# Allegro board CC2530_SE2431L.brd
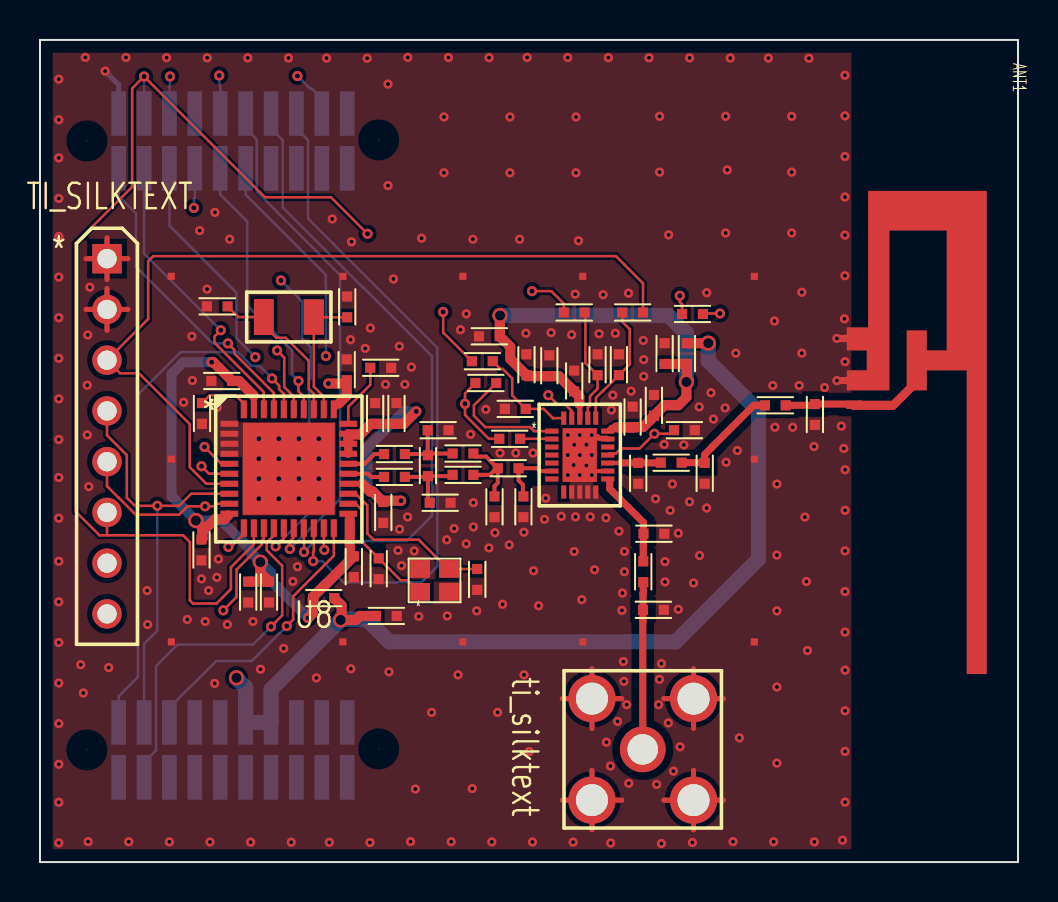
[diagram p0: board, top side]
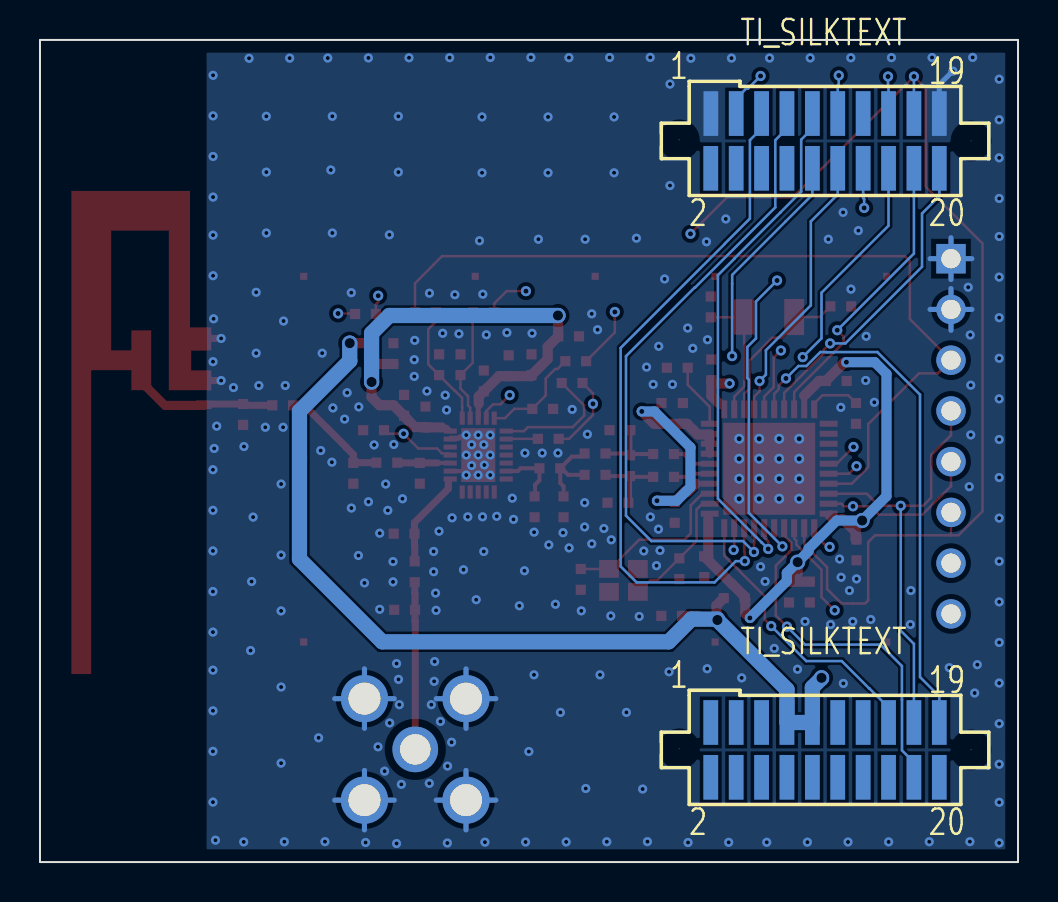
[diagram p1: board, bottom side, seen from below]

Outline 48.92 x 41.15 mm; copper layers: TOP, GND, SIGNAL_A, BOTTOM. Coordinates in mm from the lower left corner of the outline.
Outline path: rectangle 0,0 48.92,41.15

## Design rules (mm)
nets with their own width: min track width 0.356; nets N15960596 N15960606 N15982649 N15984570 VCC_SL2341 VDDRF
nets with their own width: min track width 0.508; nets VDD_CC253X

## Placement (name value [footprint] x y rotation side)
ANT1  N/A  [ANT_IIFA_CC2420_62MIL]  41.05 26.26 270 top
C1  1.0uF  [0402]  17.32 12.32 0 top
C2  1.0uF  [0402]  11.46 13.51 270 top
C3  1.0uF  [0402]  10.41 13.51 270 top
C4  1.0uF  [0402]  24.33 24.89 90 top
C5  1.0uF  [0402]  22.48 26.31 180 top
C6  12pF  [0402]  15.37 27.79 90 top
C7  12pF  [0402]  8.86 27.81 180 top
C47  1.0pF  [0402]  19.91 21.62 180 top
C48  1.0pF  [0402]  21.16 19.38 180 top
C52  2.2pF  [0402]  23.42 19.71 180 top
C62  2.2uF  [0402]  30.71 22.86 90 top
C63  100nF  [0402]  31.24 25.45 90 top
C64  10pF  [0402]  29.64 22.28 90 top
C65  10pF  [0402]  26.72 24.08 90 top
C66  2.2uF  [0402]  25.48 24.84 90 top
C71  1.8pF  [0402]  29.92 19.46 90 top
C72  1.8pF  [0402]  33.25 19.46 90 top
C76  DNI  [0402]  28.96 24.89 90 top
C77  DNI  [0402]  27.89 24.89 90 top
C79  DNI  [0402]  23.77 22.68 180 top
C83  1.8pF  [0402]  30.71 16.43 180 top
C84  1.8pF  [0402]  30.68 12.62 180 top
C85  DNI  [0402]  32.23 21.62 0 top
C101  0.1uF  [0402]  8.08 15.62 270 top
C211  0.1uF  [0402]  15.7 14.78 270 top
C221  15pF  [0402]  16.94 14.68 270 top
C231  15pF  [0402]  21.87 14.15 270 top
C241  0.1uF  [0402]  17.17 17.5 270 top
C251  18pF  [0402]  17.73 19.28 0 top
C261  18pF  [0402]  17.73 20.42 0 top
C281  0.1uF  [0402]  16.76 22.45 90 top
C282  220pF  [0402]  17.83 22.45 90 top
C311  0.1uF  [0402]  15.34 24.64 90 top
C391  1.0uF  [0402]  9.09 24.08 180 top
C401  1.0uF  [0402]  8.1 22.45 90 top
C402  TBD  [0402]  19.41 19.84 90 top
C403  TBD  [0402]  22.73 17.78 270 top
C404  TBD  [0402]  24.18 17.78 270 top
C405  TBD  [0402]  38.76 22.4 270 top
FB1  1K ohm @ 100MHz  [FB_0402]  14.2 13.21 180 top
FB2  1K ohm @ 100MHz  [FB_0402]  32.36 25.45 270 top
J5  3 GHz  [SMA_THVT_5-1814832-1]  30.15 5.64 270 top
L3  2.0nH  [0402]  20.02 17.98 0 top
L4  2.0nH  [0402]  21.16 20.45 180 top
L8  1.2nH  [0402]  31.57 19.99 180 top
L10  1.2nH  [0402]  30.18 14.53 90 top
P1  SFM-110-02-L-D-A  [CON_SMVT_2X10_50_F_SFM_FLIP_CC]  9.65 36.09 180 bottom
P2  SFM-110-02-L-D-A  [CON_SMVT_2X10_50_F_SFM_FLIP_CC]  9.65 5.61 180 bottom
P3  1x8 THVT  [HDR_THVT_1X8_100_M]  3.35 30.2 0 top
R28  2.2k  [0402]  22.3 23.98 0 top
R29  1.2k  [0402]  23.49 21.18 0 top
R32  0  [0402]  29.64 27.51 180 top
R43  0  [0402]  26.72 27.51 0 top
R45  0  [0402]  22.12 25.07 0 top
R48  0  [0402]  32.64 27.43 0 top
R301  56.2K  [0402]  17.04 24.74 0 top
R302  0  [0402]  36.78 22.86 0 top
U5  SE2431L-R  [QFN_24_EP1P70X2P70]  27 20.37 0 top
U7  CC2530F256RHA  [PVQFN_RHA40_EP4P50SQ]  12.45 19.68 270 top
U8  RF SHIELD  [SH_BMI-S-209_1P156X728]  6.07 10.52 0 top
Y5  32.768kHz  [XTAL_130X63X36]  12.45 27.28 180 top
Y6  32MHz 12pF  [XTAL_4_SM_83X67X20]  19.74 14.1 0 top

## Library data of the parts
ANT1 = ANT_IIFA_CC2420_62mil
C1-C5 = CAP_NP: alternate symbols: (0402_SMALL)
C6 C7 = CAP_NP: tolerance: 5%
C47 C48 C52 C71 C72 C83 C84 = CAP_NP: tolerance: NPO +/-0.25pF
C62-C66 C76 C77 C79 C85 C101 C211 C241 C281 C282 C311 C391 C401 = CAP0402
C221 C231 C251 C261 = CAP_NP: tolerance: +/-5%
C402-C405 = CAP_NP
FB1 FB2 = FERRITE_BEAD
J5 = SMA_5P
L3 L4 L8 L10 = IND0402
P1 P2 = CON_SMVT_2x10_50_F_SFM_FLIP_CC
P3 = HEADER_1x8
R28 R29 R32 R43 R45 R48 R302 = RES0402: tolerance: 5%
R301 = RES0402: tolerance: 1%
U5 = SE2431L_QFN24
U7 = CC2530Fxx_RHA40
U8 = RF_SHIELD_12P
Y5 = XTAL_32p768kHz_CC7V_T1A
Y6 = XTAL_4_FA-128_32MHz_10ppm_12pF

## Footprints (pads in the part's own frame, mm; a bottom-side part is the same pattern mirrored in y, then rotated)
0402
  rect 0.508x0.508 smd: 1(-0.521,0) 2(0.521,0)
ANT_IIFA_CC2420_62MIL
  rect 0.33x1.397 smd: 1(3.404,0) 2(2.108,0) 3(0,0)
CON_SMVT_2X10_50_F_SFM_FLIP_CC
  round 0.025 hole 1.346 unplated: (-7.303,0.051) (7.303,0)
  rect 0.737x2.235 smd: 1(-5.715,1.372) 2(-5.715,-1.372) 3(-4.445,1.372) 4(-4.445,-1.372) 5(-3.175,1.372) 6(-3.175,-1.372) 7(-1.905,1.372) 8(-1.905,-1.372) 9(-0.635,1.372) 10(-0.635,-1.372) 11(0.635,1.372) 12(0.635,-1.372) 13(1.905,1.372) 14(1.905,-1.372) 15(3.175,1.372) 16(3.175,-1.372) 17(4.445,1.372) 18(4.445,-1.372) 19(5.715,1.372) 20(5.715,-1.372)
FB_0402
  rect 0.508x0.508 smd: 1(-0.521,0) 2(0.521,0)
HDR_THVT_1X8_100_M
  rect 1.473x1.473 hole 0.965: 1(0,0)
  round 1.473 hole 0.965: 2(0,-2.54) 3(0,-5.08) 4(0,-7.62) 5(0,-10.16) 6(0,-12.7) 7(0,-15.24) 8(0,-17.78)
PVQFN_RHA40_EP4P50SQ
  rect 0.305x0.889 smd: 1(-2.25,-2.974) 2(-1.75,-2.974) 3(-1.25,-2.974) 4(-0.749,-2.974) 5(-0.249,-2.974) 6(0.249,-2.974) 7(0.749,-2.974) 8(1.25,-2.974) 9(1.75,-2.974) 10(2.25,-2.974) 21(2.25,2.974) 22(1.75,2.974) 23(1.25,2.974) 24(0.749,2.974) 25(0.249,2.974) 26(-0.249,2.974) 27(-0.749,2.974) 28(-1.25,2.974) 29(-1.75,2.974) 30(-2.25,2.974)
  rect 0.889x0.305 smd: 11(2.974,-2.25) 12(2.974,-1.75) 13(2.974,-1.25) 14(2.974,-0.749) 15(2.974,-0.249) 16(2.974,0.249) 17(2.974,0.749) 18(2.974,1.25) 19(2.974,1.75) 20(2.974,2.25) 31(-2.974,2.25) 32(-2.974,1.75) 33(-2.974,1.25) 34(-2.974,0.749) 35(-2.974,0.249) 36(-2.974,-0.249) 37(-2.974,-0.749) 38(-2.974,-1.25) 39(-2.974,-1.75) 40(-2.974,-2.25)
  rect 4.597x4.597 smd: 41(0,0)
QFN_24_EP1P70X2P70
  rect 0.66x0.254 smd: 1(-1.4,1.199) 2(-1.4,0.8) 3(-1.4,0.401) 4(-1.4,0) 5(-1.4,-0.401) 6(-1.4,-0.8) 7(-1.4,-1.199) 13(1.4,-1.199) 14(1.4,-0.8) 15(1.4,-0.401) 16(1.4,0) 17(1.4,0.401) 18(1.4,0.8) 19(1.4,1.199)
  rect 0.254x0.66 smd: 8(-0.8,-1.849) 9(-0.401,-1.849) 10(0,-1.849) 11(0.401,-1.849) 12(0.8,-1.849) 20(0.8,1.849) 21(0.401,1.849) 22(0,1.849) 23(-0.401,1.849) 24(-0.8,1.849)
  rect 1.702x2.692 smd: EPAD(0,0)
SH_BMI-S-209_1P156X728
  rect 0.356x0.356 smd: 1(0.5,0.5) 2(9.081,0.5) 3(15.08,0.5) 4(21.079,0.5) 5(29.66,0.5) 6(29.66,9.649) 7(29.66,18.801) 8(21.079,18.801) 9(15.08,18.801) 10(9.081,18.801) 11(0.5,18.801) 12(0.5,9.649)
SMA_THVT_5-1814832-1
  round 2.286 hole 1.524: 1(0,0)
  round 2.362 hole 1.6: 2(-2.54,2.54) 3(2.54,2.54) 4(2.54,-2.54) 5(-2.54,-2.54)
XTAL_4_SM_83X67X20
  rect 0.991x0.889 smd: 1(-0.724,-0.574) 2(0.724,-0.574) 3(0.724,0.574) 4(-0.724,0.574)
XTAL_130X63X36
  rect 0.991x1.803 smd: 1(1.25,0)
  rect 1.016x1.778 smd: 2(-1.25,0)

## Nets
GND: ANT1.2(G2) ANT1.3(G1) C1.2 C2.2 C3.2 C4.2 C5.2 C6.2 C7.2 C47.1 C62.2 C63.2 C64.2 C65.2 C66.2 C71.1 C72.1 C76.2 C77.2 C79.2 C83.1 C84.1 C85.2 C101.2 C211.2 C221.2 C231.2 C241.2 C281.2 C282.2 C311.2 C391.2 C401.1 C403.2 C404.2 C405.2 J5.2(SHIELD1) J5.3(SHIELD2) J5.4(SHIELD3) J5.5(SHIELD4) L3.2 P1.1 P1.19 P3.1 P3.2 R301.2 U5.9(GND#9) U5.10(GND#10) U5.11(GND#11) U5.12(GND#12) U5.14(GND#14) U5.18(GND#18) U5.EPAD U7.1(GND#1) U7.2(GND#2) U7.3(GND#3) U7.4(GND#4) U7.41(EPAD) U8.1(G1) U8.2(G2) U8.3(G3) U8.4(G4) U8.5(G5) U8.6(G6) U8.7(G7) U8.8(G8) U8.9(G9) U8.10(G10) U8.11(G11) U8.12(G12) Y6.2(GND#2) Y6.4(GND#4)
VCC_SL2341: C4.1 C5.1 C62.1 C63.1 C64.1 C65.1 C66.1 FB2.2 U5.19(VCC2) U5.22(VCC1)
VDD_CC253X: C2.1 C3.1 C101.1 C211.1 C241.1 C281.1 C282.1 C311.1 C391.1 FB1.2 U7.10(DVDD2) U7.21(AVDD5) U7.24(AVDD3) U7.27(AVDD2) U7.28(AVDD1) U7.29(AVDD4) U7.31(AVDD6) U7.39(DVDD1)
VDDRF: C1.1 FB1.1 FB2.1 P2.7 P2.9 P3.8
ANT_SEL: C85.1 R48.2 U5.16(ANT_SEL)
CPS: C77.1 R43.2 U5.21(CPS)
CSD: C76.1 R32.2 U5.20(CSD)
CTX: C79.1 R45.2 U5.24(CTX)
NC_4: U5.7(NC_4)
NRESET: P2.15 U7.20(RESET_N)
P0_0: P1.11 U7.19(P0_0)
P0_1: P1.5 U7.18(P0_1)
P0_2: P1.7 U7.17(P0_2)
P0_3: P1.9 U7.16(P0_3)
P0_4: P1.3 U7.15(P0_4)
P0_5: P2.18 U7.14(P0_5)
P0_6: P1.15 U7.13(P0_6)
P0_7: P1.17 P3.6 R43.1 U7.12(P0_7)
P1_0: R48.1 U7.11(P1_0)
P1_1: P3.5 R45.1 U7.9(P1_1)
P1_2: P2.17 P3.4 U7.8(P1_2)
P1_3: P3.3 R32.1 U7.7(P1_3)
P1_4: P1.14 U7.6(P1_4)
P1_5: P1.16 U7.5(P1_5)
P1_6: P1.18 U7.38(P1_6)
P1_7: P1.20 U7.37(P1_7)
P2_0: P2.19 U7.36(P2_0)
P2_1: P1.10 U7.35(P2_1)
P2_2: P1.12 U7.34(P2_2)
RF_N: C251.1 U7.25(RF_P)
RF_P: C261.1 U7.26(RF_N)
RFN2: C48.2 C251.2 C402.1 L3.1
RFP2: C47.2 C261.2 C402.2 L4.2
TR: C52.1 C404.1 U5.6(T/R)
N15887617: R301.1 U7.30(RBIAS)
N15888121: C48.1 C52.2 C403.1 L4.1
N15888255: C231.1 U7.23(XOSC_Q2) Y6.3
N15888299: C221.1 U7.22(XOSC_Q1) Y6.1
N15888951: C7.1 U7.33(P2_3/XOSC32K_Q2) Y5.1
N15888993: C6.1 U7.32(P2_4/XOSC32K_Q1) Y5.2
N15927937: R28.1 R29.1 U5.23(BOUT)
N15931758: R28.2 U5.1(B2)
N15960596: C71.2 L8.2 U5.15(ANT1)
N15960606: C72.2 L8.1 R302.1
N15982649: C83.2 L10.2 U5.13(ANT2)
N15984570: C84.2 J5.1(CENTER) L10.1
N15998457: C401.2 U7.40(DCOUPL)
N16008692: ANT1.1(FEED) C405.1 R302.2
N158961731: R29.2 U5.2(B1)

Pads without a net: P1 2 4 6 8 13; P2 1 2 3 4 5 6 8 10 11 12 13 14 16 20; P3 7; U5 3 4 5 8 17

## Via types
v1: diameter 0.508, hole 0.254, TOP to BOTTOM, 55 vias
v2: diameter 0.762, hole 0.508, TOP to BOTTOM, 7 vias
v3: diameter 0.457, hole 0.203, TOP to BOTTOM, 274 vias

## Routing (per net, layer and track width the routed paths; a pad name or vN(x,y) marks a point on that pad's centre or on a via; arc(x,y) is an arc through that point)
GND: length 135.4
  TOP w0.203: U5.14 27.68,19.57 27.64,19.53 27.64,19.41 v3(27.6,19.37)
  TOP w0.254: P3.1 3.35,31.24 ; P3.1 3.35,29.16 ; P3.1 4.4,30.2 ; P3.1 2.31,30.2 ; J5.3 32.69,4.59 ; J5.3 31.2,3.1 ; J5.3 32.69,1.61 ; J5.3 34.18,3.1 ; J5.5 29.1,8.18 ; J5.5 27.61,9.67 ; J5.5 27.61,6.69 ; J5.5 26.12,8.18 ; 31.2,8.18 J5.2 ; J5.2 34.18,8.18 ; J5.2 32.69,9.67 ; J5.2 32.69,6.69 ; J5.4 27.61,4.59 ; J5.4 29.1,3.1 ; J5.4 27.61,1.61 ; J5.4 26.12,3.1 ; v3(27.6,21.37) 27.69,21.29 27.9,21.29 27.97,21.21 28.36,21.21 U5.18 ; 2.31,27.66 P3.2 ; P3.2 3.35,28.7 ; P3.2 3.35,26.62 ; P3.2 4.4,27.66
  TOP w0.356: ANT1.2 41.05,24.1 v3(39.86,24.1) ; ANT1.3 41.05,26.21 v3(39.86,26.21)
  GND w0.254: P3.2 4.4,27.66 ; P3.2 2.31,27.66 ; P3.2 3.35,28.7 ; P3.2 3.35,26.62 ; J5.2 32.69,9.67 ; J5.2 32.69,6.69 ; J5.2 34.18,8.18 ; J5.2 31.2,8.18 ; 3.35,29.16 P3.1 ; P3.1 4.4,30.2 ; P3.1 2.31,30.2 ; P3.1 3.35,31.24 ; J5.3 34.18,3.1 ; J5.3 31.2,3.1 ; J5.3 32.69,4.59 ; J5.3 32.69,1.61 ; J5.5 27.61,9.67 ; J5.5 29.1,8.18 ; J5.5 26.12,8.18 ; J5.5 27.61,6.69 ; 27.61,1.61 J5.4 ; J5.4 29.1,3.1 ; J5.4 26.12,3.1 ; J5.4 27.61,4.59
  SIGNAL_A w0.254: 2.31,30.2 P3.1 ; P3.1 3.35,29.16 ; P3.1 3.35,31.24 ; P3.1 4.4,30.2 ; J5.3 32.69,4.59 ; J5.3 32.69,1.61 ; J5.3 31.2,3.1 ; J5.3 34.18,3.1 ; 2.31,27.66 P3.2 ; P3.2 3.35,26.62 ; P3.2 3.35,28.7 ; P3.2 4.4,27.66 ; J5.5 29.1,8.18 ; J5.5 27.61,9.67 ; J5.5 27.61,6.69 ; J5.5 26.12,8.18 ; 31.2,8.18 J5.2 ; J5.2 34.18,8.18 ; J5.2 32.69,6.69 ; J5.2 32.69,9.67 ; 27.61,1.61 J5.4 ; J5.4 26.12,3.1 ; J5.4 27.61,4.59 ; J5.4 29.1,3.1
  BOTTOM w0.254: J5.3 32.69,4.59 ; J5.3 34.18,3.1 ; J5.3 31.2,3.1 ; J5.3 32.69,1.61 ; 3.35,26.62 P3.2 ; P3.2 2.31,27.66 ; P3.2 4.4,27.66 ; P3.2 3.35,28.7 ; 3.35,29.16 P3.1 ; P3.1 3.35,31.24 ; P3.1 4.4,30.2 ; P3.1 2.31,30.2 ; J5.5 27.61,9.67 ; J5.5 27.61,6.69 ; J5.5 29.1,8.18 ; J5.5 26.12,8.18 ; 31.2,8.18 J5.2 ; J5.2 34.18,8.18 ; J5.2 32.69,9.67 ; J5.2 32.69,6.69 ; 27.61,1.61 J5.4 ; J5.4 29.1,3.1 ; J5.4 26.12,3.1 ; J5.4 27.61,4.59 ; v3(3.26,39.59) 3.94,38.91 P1.19
  vias: v1(10.94,21.19) v1(10.94,20.19) v1(10.94,19.18) v1(10.94,18.18) v1(11.95,21.19) v1(11.95,20.19) v1(11.95,19.18) v1(11.95,18.18) v1(12.95,21.19) v1(12.95,20.19) v1(12.95,19.18) v1(12.95,18.18) v1(13.95,21.19) v1(13.95,20.19) v1(13.95,19.18) v1(13.95,18.18) v3(0.94,39.18) v3(0.94,37.15) v3(0.94,35.25) v3(0.94,33.22) v3(0.94,31.31) v3(0.94,29.28) v3(0.94,27.25) v3(0.94,25.21) v3(0.94,23.18) v3(0.94,21.15) v3(0.94,19.25) v3(0.94,17.21) v3(0.94,15.05) v3(0.94,13.02) v3(0.94,10.99) v3(0.94,8.96) v3(0.94,6.93) v3(0.94,4.89) v3(0.94,2.99) v3(0.94,0.96) v3(2.04,9.88) v3(2.17,8.46) v3(2.27,40.27) v3(2.39,26.38) v3(2.36,23.87) v3(2.36,21.38) v3(2.41,1.02) v3(2.49,28.77) v3(2.44,18.79) v3(3.44,9.73) v3(4.3,40.27) v3(4.44,1.02) v3(5.36,13.59) v3(5.38,11.89) v3(6.33,40.26) v3(6.47,1.01) v3(7.19,23.01) v3(7.37,12.14) v3(7.59,26.31) v3(7.62,24.1) v3(7.99,31.61) v3(8.08,14.17) v3(8.27,12.04) v3(8.36,40.26) v3(8.36,28.68) v3(8.43,13.59) v3(8.5,1) v3(8.75,32.52) v3(8.74,8.94) v3(8.86,22.76) v3(8.85,14.25) v3(8.93,15.17) v3(9.37,11.89) v3(9.49,31.17) v3(10.4,40.25) v3(10.54,1) v3(10.65,12.04) v3(11.03,9.65) v3(12.19,10.69) v3(12.43,40.24) v3(12.57,0.99) v3(12.65,14.05) v3(12.88,14.78) v3(13.82,9.22) v3(14.33,40.24) v3(14.47,0.99) v3(14.62,32.19) v3(15.58,31.05) v3(15.53,26.14) v3(15.55,9.67) v3(16.27,25.71) v3(16.37,40.23) v3(16.5,0.98) v3(16.52,26.73) v3(17.28,23.91) v3(17.41,38.94) v3(17.41,33.86) v3(17.45,9.52) v3(17.68,29.18) v3(17.91,15.6) v3(17.97,25.81) v3(17.98,16.66) v3(18.08,14.83) v3(18.25,23.91) v3(18.4,40.27) v3(18.39,17.27) v3(18.58,24.77) v3(18.54,1.02) v3(18.72,15.57) v3(18.78,3.66) v3(18.95,12.29) v3(19.09,31.22) v3(19.59,7.49) v3(20.21,37.29) v3(20.21,34.5) v3(20.35,16.13) v3(20.37,12.32) v3(20.43,40.27) v3(20.57,1.02) v3(20.71,16.7) v3(20.91,9.37) v3(21.03,26.64) v3(21.32,27.44) v3(21.32,15.93) v3(21.54,21.41) v3(21.65,31.17) v3(21.68,17.99) v3(21.68,16.77) v3(21.62,3.68) v3(21.84,12.57) v3(22.3,22.66) v3(22.46,40.26) v3(22.45,15.72) v3(22.6,1.01) v3(22.76,16.48) v3(22.89,7.49) v3(23.01,20.47) v3(23.14,12.9) v3(23.51,37.29) v3(23.51,34.5) v3(23.47,15.88) v3(23.8,20.47) v3(23.99,31.17) v3(24.21,16.51) v3(24.21,9.37) v3(24.31,26.47) v3(24.37,40.27) v3(24.47,5.53) v3(24.66,20.47) v3(24.69,14.58) v3(24.63,1) v3(24.94,12.83) v3(25.3,18.21) v3(25.23,17.15) v3(25.57,26.5) v3(26.07,17.31) v3(26.4,40.27) v3(26.4,21.37) v3(26.4,20.37) v3(26.4,19.37) v3(26.59,26.39) v3(26.7,19.87) v3(26.66,1) v3(26.81,37.29) v3(26.81,34.5) v3(26.77,28.42) v3(26.72,20.89) v3(26.78,17.28) v3(26.72,15.54) v3(26.94,31.1) v3(27,21.37) v3(27,20.37) v3(27,19.37) v3(27.1,13.13) v3(27.33,20.89) v3(27.33,19.85) v3(27.6,20.37) v3(27.52,17.28) v3(27.74,14.63) v3(27.97,26.44) v3(28.17,28.4) v3(28.31,17.23) v3(28.33,6) v3(28.43,40.26) v3(28.58,22.63) v3(28.53,4.8) v3(28.54,0.95) v3(28.65,23.37) v3(28.78,26.47) v3(28.89,7.04) v3(28.96,16.56) v3(29.11,12.6) v3(29.13,13.46) v3(29.18,10.04) v3(29.2,9.04) v3(29.23,15.55) v3(29.23,14.53) v3(29.35,7.88) v3(29.44,28.47) v3(29.45,3.94) v3(29.57,23.57) v3(30.18,26.11) v3(30.2,25.15) v3(30.2,24.31) v3(30.46,40.26) v3(30.79,18.18) v3(30.85,3.89) v3(31,37.33) v3(31,34.53) v3(30.99,9.14) v3(30.95,7.88) v3(31.08,9.93) v3(31.08,0.93) v3(31.22,20.9) v3(31.26,15.04) v3(31.26,14.02) v3(31.45,31.39) v3(31.43,6.96) v3(31.52,17.6) v3(31.63,18.92) v3(31.68,4.55) v3(31.93,16.46) v3(31.93,12.65) v3(32.01,5.77) v3(32.21,20.88) v3(32.49,40.25) v3(32.49,18.03) v3(32.69,13.97) v3(32.63,0.98) v3(32.97,22.78) v3(32.99,15.34) v3(33.35,28.5) v3(33.35,17.72) v3(33.56,23.49) v3(33.69,22.17) v3(34.3,37.33) v3(34.3,31.49) v3(34.27,22.73) v3(34.37,34.64) v3(34.32,20.01) v3(34.53,40.24) v3(34.67,1.02) v3(34.81,25.47) v3(34.88,20.6) v3(34.98,6.22) v3(36.43,40.24) v3(36.65,23.85) v3(36.7,1.02) v3(36.74,27.08) v3(36.76,21.76) v3(36.86,18.92) v3(36.86,15.36) v3(36.86,12.57) v3(36.86,8.76) v3(36.86,4.95) v3(37.6,37.33) v3(37.6,34.53) v3(37.6,31.49) v3(37.65,21.76) v3(37.97,23.85) v3(38.11,28.52) v3(38.11,25.47) v3(38.26,17.27) v3(38.34,14.04) v3(38.39,10.59) v3(38.46,40.23) v3(38.72,20.8) v3(38.73,1.01) v3(39.24,23.75) v3(40.08,21.82) v3(40.21,20.7) v3(40.14,1.09) v3(40.26,39.38) v3(40.26,37.35) v3(40.26,35.32) v3(40.26,33.28) v3(40.26,31.38) v3(40.26,29.35) v3(40.24,27.19) v3(40.27,25.04) v3(40.27,19.64) v3(40.27,17.6) v3(40.27,15.57) v3(40.27,13.54) v3(40.27,11.51) v3(40.27,9.6) v3(40.27,7.57) v3(40.27,5.54) v3(40.27,3)
VCC_SL2341: length 27.3
  TOP w0.254: 28.83,21.76 28.59,21.76 U5.19 ; U5.22 27,22.91 26.97,22.94
  TOP w0.508: 28.83,21.76 C64.1 29.66,21.77 30.17,21.77 30.51,22.11 30.51,22.11 30.66,22.26 30.66,22.29 C62.1 31.23,22.87 31.93,22.87 32.33,23.27 v2(32.33,24.03) 32.36,24.03 FB2.2 C63.1 ; v2(23.01,27.36) 23,27.36 C5.1 23.53,25.79 23.53,25.18 C4.1 24.33,24.32 C66.1 25.96,24.32 C65.1 26.97,23.3 26.97,22.94
  BOTTOM w0.762: v2(23.01,27.36) 31.45,27.36 32.33,26.47 v2(32.33,24.03)
VDD_CC253X: length 67
  TOP w0.254: 15.49,17.14 15.49,17.43 U7.21 ; U7.24 16.12,18.94 ; U7.31 14.96,22.92 14.96,22.96 ; U7.10 9.42,17.38 9.42,17.35 ; U7.39 10.7,23.34
  TOP w0.356: 15.42,21.4 U7.29
  TOP w0.406: U7.28 U7.27
  TOP w0.508: 16.12,18.94 16.51,18.55 16.64,18.55 C241.1 17.17,18.08 v1(18.06,18.08) ; U7.28 15.42,21.4 16.02,21.4 16.25,21.62 16.25,21.63 16.55,21.93 C281.1 C282.1 18.2,21.93 v1(18.82,22.56) ; 14.96,22.96 15.34,23.34 15.34,23.95 ; C101.1 8.13,16.2 8.13,16.54 ; C3.1 C2.1 11.02,14.47 v2(11.02,15.01) ; v1(8.59,25.02) 8.67,25.02 C391.1 9.96,24.08 10.7,23.34 ; 8.13,16.54 8.13,16.76 v2(7.8,17.09) ; 8.13,16.54 8.75,17.16 9.22,17.16 9.42,17.35 ; 15.49,17.14 15.49,15.3 C211.1 14.32,13.92 14.31,13.92 13.68,13.3 FB1.2 13.64,13.17 13.64,12.45 v1(13.41,12.22) ; 15.34,23.95 C311.1 ; 15.34,23.95 v1(14.43,23.95)
  SIGNAL_A w0.508: v1(18.82,22.56) 18.37,23 16.11,23 15.16,23.95 v1(14.43,23.95) ; v1(13.41,12.22) 14.05,12.22 14.2,12.37 14.23,12.37 15.39,13.53 17.89,13.53 19.61,15.24 19.61,17.17 18.69,18.08 v1(18.06,18.08)
  BOTTOM w0.508: v1(18.82,22.56) 18.19,22.56 16.38,20.75 16.38,18.77 17.07,18.08 v1(18.06,18.08) ; v1(8.59,25.02) 7.17,25.02 6.58,24.43 6.58,18.31 v2(7.8,17.09) 9.07,17.09 10.48,15.68 10.48,15.55 v2(11.02,15.01) 11.56,14.47 11.56,14.06 v1(13.41,12.22)
VDDRF: length 57.2
  TOP w0.508: C1.1 16,12.32 15.8,12.12 v2(15.04,12.12) 15.09,12.17 15.09,12.84 FB1.1 ; FB2.1 v2(33.43,25.97)
  SIGNAL_A w0.762: v2(9.83,9.22) 8.84,10.21 5.56,10.21 P3.8
  BOTTOM w0.762: v2(33.43,25.97) 33.43,25.08 35.94,22.57 35.94,15.16 31.8,11.02 17.48,11.02 16.34,12.16 15.04,12.16 v2(15.04,12.12) 11.56,8.64 P2.7 10.29,6.98 10.29,8.74 9.83,9.19 v2(9.83,9.22)
ANT_SEL: length 12.1
  TOP w0.127: C85.1 31.53,21.44 v1(30.73,21.44) 30,20.7 29.06,20.7 28.81,20.45 28.48,20.45 U5.16 ; v1(34.01,27.46) 33.16,27.46 R48.2
  SIGNAL_A w0.127: v1(30.73,21.44) 34.01,24.71 v1(34.01,27.46)
CPS: length 5.8
  TOP w0.127: R43.2 27.28,27.51 27.28,24.98 C77.1 27.89,23.7 27.56,23.37 27.56,23.35 27.51,23.3 27.51,22.85 27.4,22.74 U5.21
CSD: length 6.2
  TOP w0.127: R32.2 29.12,27.05 29.5,26.67 29.5,24.91 C76.1 28.18,23.6 28.17,23.6 27.81,23.24 27.81,22.76 27.8,22.76 U5.20
CTX: length 5.2
  TOP w0.127: R45.2 23.04,24.68 23.15,24.68 23.62,24.21 23.62,23.36 C79.1 25.2,22.68 25.66,22.22 U5.24
NRESET: length 14.2
  TOP w0.127: v1(12.34,11.81) 12.66,12.13 12.66,13.3 14.7,15.33 U7.20
  BOTTOM w0.127: P2.15 6.48,7.73 7.44,8.69 7.45,8.69 8.81,10.06 10.59,10.06 v1(12.34,11.81)
P0_0: length 40.3
  TOP w0.127: v1(14.22,15.62) 14.2,15.65 U7.19
  SIGNAL_A w0.127: v1(8.97,39.37) 5.28,35.69 5.28,14.97 7.14,13.11 12.78,13.11 14.22,14.55 v1(14.22,15.62)
  BOTTOM w0.127: v1(8.97,39.37) 8.97,38.92 9.02,38.87 P1.11
P0_1: length 34.2
  TOP w0.127: v1(13.67,15.06) 13.67,15.51 13.7,15.54 U7.18
  BOTTOM w0.127: P1.5 12.83,36.72 13.41,36.13 13.41,32.21 14.67,30.94 14.67,30.94 19.88,25.74 19.88,14.8 19.08,14 15.18,14 14.11,15.06 v1(13.67,15.06)
P0_2: length 31.8
  TOP w0.127: U7.17 13.2,15.98 13.21,15.96 v1(13.21,15.52)
  BOTTOM w0.127: P1.7 11.56,36.72 12.14,36.13 12.14,32.77 16.15,28.76 16.15,28.76 16.2,28.74 19.61,25.32 19.61,17.34 18.34,16.07 13.75,16.07 v1(13.21,15.52)
P0_3: length 25.9
  TOP w0.127: v1(12.5,15.67) 12.5,16.05 12.69,16.25 U7.16
  BOTTOM w0.127: v1(12.5,15.67) 12.81,15.99 12.82,15.99 15.01,18.18 15.01,29.37 14.2,30.19 14.2,30.2 11.89,32.51 11.89,32.51 10.85,33.55 10.85,36.16 10.29,36.72 10.29,37.47
P0_4: length 29.9
  TOP w0.127: U7.15 12.2,16.21 v1(11.79,15.8)
  SIGNAL_A w0.127: v1(12.05,29.11) 10.69,30.47 10.69,37.16 v1(12.88,39.34)
  BOTTOM w0.127: P1.3 14.1,38.21 13.59,38.72 13.5,38.72 v1(12.88,39.34) ; v1(11.79,15.8) 13.46,17.48 13.46,24.14 13.54,24.22 13.54,25.78 13.11,26.21 13.11,28.05 v1(12.05,29.11)
P0_5: length 18
  TOP w0.127: U7.14 11.7,16.34 11.45,16.1 11.45,16.09 11.34,15.98 11.34,15.61 11.45,15.5 11.45,15.5 12.12,14.83 12.12,12.34 v1(11.56,11.79)
  BOTTOM w0.127: v1(11.56,11.79) 10.66,10.88 6.88,10.88 5.81,9.81 5.81,8.12 5.8,8.12 5.8,5.59 5.21,4.99 P2.18
P0_6: length 37.1
  TOP w0.127: U7.13 11.2,16.2 11.09,16.09 11.09,15.89 10.43,15.23 10.43,15.23 9.83,14.63 9.83,13.26 v1(9.17,12.6)
  SIGNAL_A w0.127: v1(9.17,12.6) 7.21,12.6 4.9,14.91 4.9,37.72 v1(6.5,39.32)
  BOTTOM w0.127: v1(6.5,39.32) 6.5,38.87 6.48,38.85 P1.15
P0_7: length 67.5
  TOP w0.127: 3.35,16.36 7.15,16.36 7.5,16.01 7.5,13.14 7.5,13.13 7.5,13.09 7.65,12.94 8.27,12.94 8.27,12.94 8.83,12.94 9.55,13.67 9.55,14.76 10.7,15.9 U7.12 ; 3.35,16.36 P3.6 ; 3.35,16.36 2.97,16.36 1.78,17.55 1.78,30.96 4.61,33.79 4.61,38.72 v1(5.21,39.32) 11.25,33.27 14.55,33.27 v1(16.38,31.45) ; v1(24.61,28.58) 25.58,28.58 26.2,27.96 R43.1
  SIGNAL_A w0.127: v1(16.38,31.45) 18.75,29.08 24.1,29.08 v1(24.61,28.58)
  BOTTOM w0.127: P1.17 v1(5.21,39.32)
P1_0: length 30.1
  TOP w0.127: U7.11 10.2,16.42 9.55,15.77 v1(9.42,15.77) ; R48.1 32.12,27.91 32,28.03 v1(32,28.35)
  SIGNAL_A w0.127: v1(9.42,15.77) 10.41,16.76 14.48,16.76 20.32,22.61 20.32,22.63 21.07,23.38 21.07,23.39 23.22,25.53 28.45,25.53 31.27,28.35 v1(32,28.35)
P1_1: length 35.7
  TOP w0.127: U7.9 8.83,17.93 8.7,17.81 v1(8.25,17.81) 7.38,17.81 6.96,17.39 4.79,17.39 3.95,18.22 3.95,18.22 3.94,18.23 3.94,18.23 3.36,18.81 3.36,18.82 3.35,18.82 P3.5 ; R45.1 20.17,26.5 v1(20.17,27.53)
  SIGNAL_A w0.127: v1(8.25,17.81) 8.6,18.15 8.6,19.11 8.6,19.11 8.6,19.92 8.19,20.33 8.01,20.33 6.6,21.74 6.6,26.37 8.71,28.47 19.23,28.47 v1(20.17,27.53)
P1_2: length 21.4
  TOP w0.127: U7.8 7.56,18.44 6.96,17.83 v1(5.87,17.83) 4.75,17.83 4.34,18.24 4.34,20.37 3.35,21.36 P3.4
  BOTTOM w0.127: v1(5.87,17.83) 5.87,11.58 5.21,10.92 P2.17
P1_3: length 42.6
  TOP w0.127: U7.7 8.32,18.94 7.49,19.76 7.49,21.92 4.95,24.46 4.01,24.46 P3.3 5.41,27.18 5.41,30.07 5.66,30.33 28.81,30.33 29.24,29.9 29.24,29.89 30.16,28.97 R32.1
P1_4: length 17.9
  TOP w0.127: U7.6 8.45,19.44 v1(8.08,19.81)
  SIGNAL_A w0.127: v1(8.08,19.81) 6.2,21.69 6.2,31.24 v1(7.7,32.74)
  BOTTOM w0.127: P1.14 7.75,33.24 7.7,33.19 v1(7.7,32.74)
P1_5: length 18.9
  TOP w0.127: v1(8.23,20.78) 9.07,19.93 U7.5
  SIGNAL_A w0.127: v1(8.23,20.78) 8.23,23.66 9.84,25.27 v1(10.77,25.27)
  BOTTOM w0.127: v1(10.77,25.27) 9.83,26.21 9.83,28.5 6.48,31.85 P1.16
P1_6: length 14.8
  TOP w0.127: v1(9.04,26.62) 8.72,26.3 8.72,26 11.2,23.53 U7.38
  BOTTOM w0.127: v1(9.04,26.62) 5.21,30.45 P1.18
P1_7: length 15.7
  TOP w0.127: v1(9.4,25.96) 9.72,25.64 9.72,25.46 11.7,23.48 U7.37
  BOTTOM w0.127: v1(9.4,25.96) 8.64,25.96 4.8,29.79 4.8,32.46 3.94,33.32 P1.20
P2_0: length 26.7
  TOP w0.127: v1(11.61,24.21) 11.93,23.89 11.93,23.88 11.96,23.85 11.96,23.67 12.2,23.43 U7.36
  BOTTOM w0.127: v1(11.61,24.21) 10.99,24.83 10.58,24.83 9.89,25.53 9.6,25.53 9.58,25.51 9.21,25.51 9.2,25.53 7.04,25.53 4.9,23.39 4.9,9.26 3.94,8.3 P2.19
P2_1: length 16.9
  TOP w0.127: v1(11.86,25.6) 12.22,25.25 12.22,23.77 12.69,23.3 U7.35
  SIGNAL_A w0.127: v1(14.3,25.32) 12.59,25.32 12.31,25.6 v1(11.86,25.6)
  BOTTOM w0.127: 10.29,34.72 10.29,33.4 11.63,32.05 14.3,29.39 14.3,28.95 14.3,28.95 v1(14.3,25.32)
P2_2: length 13.8
  TOP w0.127: U7.34 13.2,23.3 12.93,23.56 v1(12.93,24.08)
  BOTTOM w0.127: P1.12 9.02,33.41 10.36,32.06 10.36,27.86 12.61,25.62 12.61,24.4 v1(12.93,24.08)
RF_N: length 1.9
  TOP w0.203: U7.25 16.4,19.44 16.56,19.28 C251.1
RF_P: length 2
  TOP w0.203: U7.26 16.24,19.93 16.73,20.42 C261.1
RFN2: length 3.8
  TOP w0.203: C48.2 20.57,19.32 C402.1 19.41,19.28 ; L3.1 19.41,17.98 19.41,19.28 ; 19.41,19.28 C251.2
RFP2: length 3.8
  TOP w0.203: C47.2 19.39,20.36 C402.2 19.43,20.36 19.43,20.42 ; L4.2 19.43,20.45 19.43,20.42 ; 19.43,20.42 C261.2
TR: length 3.2
  TOP w0.203: U5.6 25.02,19.57 24.88,19.71 C52.1 23.94,19.1 24.16,18.88 24.16,18.3 C404.1
N15887617: length 3.3
  TOP w0.127: R301.1 16.52,23.89 15.42,22.79 U7.30
N15888121: length 4.4
  TOP w0.203: C48.1 22.5,19.38 22.83,19.71 C52.2 ; L4.1 21.83,20.29 22.31,20.29 C52.2 ; C52.2 22.9,18.97 22.73,18.81 C403.1
N15888255: length 8.8
  TOP w0.127: U7.23 15.79,18.44 16.37,17.85 16.37,16.44 16.68,16.13 18.95,16.13 20.41,14.67 Y6.3 20.46,14.67 C231.1
N15888299: length 6.3
  TOP w0.127: Y6.1 18.96,13.52 18.38,14.1 18.04,14.1 C221.1 16.08,16.07 16.08,17.65 15.79,17.93 U7.22
N15888951: length 8
  TOP w0.127: C7.1 9.92,27.28 Y5.1 11.2,26.87 11.83,26.24 12.29,26.24 13.44,25.09 13.44,23.69 13.7,23.44 U7.33
N15888993: length 6.5
  TOP w0.127: 13.7,27.27 Y5.2 ; 13.7,27.27 C6.1 ; 13.7,27.27 13.7,23.8 14.2,23.3 U7.32
N15927937: length 10.2
  TOP w0.127: v1(25.43,23.37) 25.88,22.91 26.26,22.91 26.6,22.58 U5.23 ; R29.1 22.45,21.18 21.26,22.38 v1(21.26,22.94) 21.26,23.46 R28.1
  SIGNAL_A w0.127: v1(25.43,23.37) 21.69,23.37 v1(21.26,22.94)
N15931758: length 6.3
  TOP w0.127: R28.2 21.7,22.86 21.7,22.34 22.28,21.77 24.51,21.77 24.71,21.57 U5.1
N15960596: length 2.7
  TOP w0.203: U5.15 28.41,19.98 29.03,19.98
  TOP w0.356: L8.2 31.05,19.98 C71.2 29.03,19.98
N15960606: length 5.6
  TOP w0.356: R302.1 35.7,22.86 33.62,20.78 33.62,20.76 33.25,20.4 33.25,19.99 ; 33.25,19.99 L8.1 ; 33.25,19.99 C72.2
N15982649: length 4.9
  TOP w0.203: U5.13 28.5,19.08
  TOP w0.356: L10.2 30.18,15.88 30.19,15.88 C83.2 30.19,16.99 28.5,18.68 28.5,19.08
N15984570: length 8.4
  TOP w0.356: L10.1 30.18,13.45 30.16,13.45 C84.2 30.16,12.07 30.15,12.07 J5.1
N15998457: length 2.7
  TOP w0.127: U7.40 10.2,22.95 9.78,23.37 8.49,23.37 C401.2
N16008692: length 3.9
  TOP w0.356: ANT1.1 41.05,22.92 C405.1 38.76,22.86 R302.2
N158961731: length 1.6
  TOP w0.127: R29.2 25.6,21.18 U5.2

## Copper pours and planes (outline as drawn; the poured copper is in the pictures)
GND on TOP (solid shape): 47.35,9.41 46.35,9.41 46.35,24.61 44.35,24.61 44.35,23.61 43.35,23.61 43.35,26.61 44.35,26.61 44.35,25.61 45.35,25.61 45.35,31.61 42.49,31.61 42.49,23.61 40.35,23.61 40.35,24.61 41.35,24.61 41.35,25.61 40.35,25.61 40.35,26.76 41.42,26.76 41.42,33.59 47.35,33.59
GND on TOP: 0.64,0.64 0.64,40.51 40.59,40.51 40.59,0.64 ; 7 cut-outs
GND on BOTTOM, GND, SIGNAL_A: 0.64,0.64 0.64,40.51 40.59,40.51 40.59,0.64
N16008692 on TOP (solid shape): 43.74,23.7 43.74,23.62 42.75,22.63 40.59,22.63 40.59,22.68 40.34,22.68 40.34,23.09 42.6,23.09 43.36,23.85 43.59,23.85
